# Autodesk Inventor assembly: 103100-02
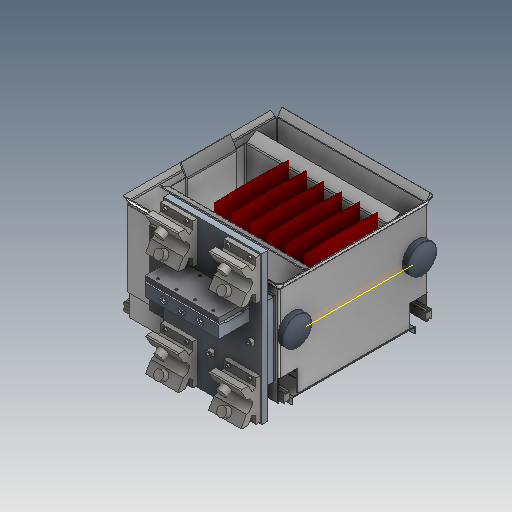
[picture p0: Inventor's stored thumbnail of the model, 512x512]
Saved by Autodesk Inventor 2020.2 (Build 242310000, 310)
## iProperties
Created: 2000-10
Part Number: 103100-02
Document SubType Name: Assembly
Designer: wymerj
Mass: 14269.6 g
Surface Area: 19861.8 cm^2
Volume: 4078.28 cm^3
Density: 3.49893 g/cm^3
Control State: 0
Master: False
Checked Out: False
Shininess: 0.0
Length Units: 11269
Angle Units: 11279
Time Units: 11290
Mass Units: 11283
Length Display Precision: 3
Angle Display Precision: 2
Compacted: True
Dimensions: 394,2x458,1x394,7 mm
Mass: 14,27 kg
DocNumber: ADSK-014244
Folder: 01 - Themengebiete\Simplification\01 - Packaging machine\
VDS_Category: 3D Komponenten
VDS_NumSchm: Autodesk
Density: 0.0
Volumn: 0.0
Area: 0.0
PropertySet Name: Model Information
Author: wymerj
Revision Number: -
Title: skid
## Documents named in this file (14)
- D:\07 - DEMODATEN\OTX 2019 - Dataset - UPDATE - Dez2019\Designs\07-Packing machine\103100-02.iam
- D:\07 - DEMODATEN\OTX 2019 - Dataset - UPDATE - Dez2019\Designs\07-Packing machine\500361.iam
- D:\07 - DEMODATEN\OTX 2019 - Dataset - UPDATE - Dez2019\Designs\07-Packing machine\500693.iam
- D:\07 - DEMODATEN\OTX 2019 - Dataset - UPDATE - Dez2019\Designs\07-Packing machine\Parts\ADSK-011742.ipt
- D:\07 - DEMODATEN\OTX 2019 - Dataset - UPDATE - Dez2019\Designs\07-Packing machine\Parts\ADSK-011668.ipt
- D:\07 - DEMODATEN\OTX 2019 - Dataset - UPDATE - Dez2019\Designs\07-Packing machine\Parts\ADSK-011673.ipt
- D:\07 - DEMODATEN\OTX 2019 - Dataset - UPDATE - Dez2019\Content Center Files\de-DE\DIN 125-1  B\DIN 125-1 - B 8,4.ipt
- D:\07 - DEMODATEN\OTX 2019 - Dataset - UPDATE - Dez2019\Content Center Files\de-DE\ISO 4762(2)\ISO 4762 - M8 x 25ISO.ipt
- D:\07 - DEMODATEN\OTX 2019 - Dataset - UPDATE - Dez2019\Content Center Files\de-DE\ISO 4762(2)\ISO 4762 - M8 x 80ISO.ipt
- D:\07 - DEMODATEN\OTX 2019 - Dataset - UPDATE - Dez2019\Content Center Files\de-DE\DIN 125-1  B\DIN 125-1 - B 4,3.ipt
- D:\07 - DEMODATEN\OTX 2019 - Dataset - UPDATE - Dez2019\Designs\07-Packing machine\Parts\ADSK-011759.ipt
- D:\07 - DEMODATEN\OTX 2019 - Dataset - UPDATE - Dez2019\Content Center Files\de-DE\ISO 4762(2)\ISO 4762 - M4 x 20ISO.ipt
- D:\07 - DEMODATEN\OTX 2019 - Dataset - UPDATE - Dez2019\Content Center Files\de-DE\ISO 4762(2)\ISO 4762 - M6 x 30ISO.ipt
- D:\07 - DEMODATEN\OTX 2019 - Dataset - UPDATE - Dez2019\Designs\07-Packing machine\ADSK-014245.iam
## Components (59 placed, 13 different names)
1. 500361:1 [sub-assembly] — Mate:1, Mate:2, Mate:3, Insert:1, Mate:4, Insert:2, Mate:5, Insert:3, Mate:6, Insert:4, Mate:7, Passend:12, Passend:13, Passend:14
2. 500693:1 [sub-assembly] — Mate:1, Mate:2, Mate:3, Passend:66, Passend:67, Passend:68
3. ADSK-011742:1 — Insert:3, Mate:6
4. ADSK-011742:2 — Insert:1, Mate:4
5. ADSK-011742:3 — Insert:2, Mate:5
6. ADSK-011742:4 — Insert:4, Mate:7
7. ADSK-011668:1 — Passend:9, Passend:10, Passend:11, Passend:12, Passend:13, Passend:14, Passend:16, Passend:18, Passend:20, Passend:22, Passend:24, Passend:26, Passend:28, Passend:30, Passend:31, Passend:33
8. ADSK-011673:1 — Passend:9, Passend:10, Passend:11, Passend:32
9. ADSK-014245:1 [sub-assembly] — Passend:66, Passend:67, Passend:68
10. ADSK-011759:1 — Passend:31, Passend:32, Passend:33
11. ISO 4762 M4 x 20:1 — Passend:35
12. ISO 4762 M4 x 20:2 — Passend:37
13. ISO 4762 M4 x 20:3 — Passend:39
14. ISO 4762 M4 x 20:4 — Passend:41
15. ISO 4762 M4 x 20:5 — Passend:43
16. ISO 4762 M4 x 20:6 — Passend:45
17. ISO 4762 M4 x 20:7 — Passend:47
18. ISO 4762 M4 x 20:8 — Passend:49
19. ISO 4762 M4 x 20:9 — Passend:51
20. ISO 4762 M4 x 20:10 — Passend:53
21. ISO 4762 M4 x 20:11 — Passend:55
22. ISO 4762 M4 x 20:12 — Passend:57
23. ISO 4762 M4 x 20:13 — Passend:59
24. ISO 4762 M4 x 20:14 — Passend:61
25. ISO 4762 M4 x 20:15 — Passend:63
26. ISO 4762 M4 x 20:16 — Passend:65
27. DIN 125-1 B B 8,4:1
28. DIN 125-1 B B 8,4:3
29. DIN 125-1 B B 8,4:4
30. ISO 4762 M8 x 25:1
31. ISO 4762 M8 x 25:2
32. ISO 4762 M8 x 25:3
33. ISO 4762 M8 x 80:1
34. ISO 4762 M8 x 80:2
35. ISO 4762 M8 x 80:3
36. DIN 125-1 B B 4,3:1
37. DIN 125-1 B B 4,3:2 — Passend:51, Passend:53, Passend:55, Passend:57
38. DIN 125-1 B B 4,3:3
39. DIN 125-1 B B 4,3:4
40. DIN 125-1 B B 4,3:5
41. DIN 125-1 B B 4,3:6 — Passend:59, Passend:61, Passend:63, Passend:65
42. DIN 125-1 B B 4,3:7
43. DIN 125-1 B B 4,3:8
44. DIN 125-1 B B 4,3:9
45. DIN 125-1 B B 4,3:10
46. DIN 125-1 B B 4,3:11
47. DIN 125-1 B B 4,3:12 — Passend:43, Passend:45, Passend:47, Passend:49
48. DIN 125-1 B B 4,3:13
49. DIN 125-1 B B 4,3:14 — Passend:35, Passend:37, Passend:39, Passend:41
50. DIN 125-1 B B 4,3:15
51. DIN 125-1 B B 4,3:16
52. ISO 4762 M6 x 30:1 — Passend:16
53. ISO 4762 M6 x 30:2 — Passend:18
54. ISO 4762 M6 x 30:3 — Passend:20
55. ISO 4762 M6 x 30:4 — Passend:22
56. ISO 4762 M6 x 30:5 — Passend:24
57. ISO 4762 M6 x 30:6 — Passend:26
58. ISO 4762 M6 x 30:7 — Passend:28
59. ISO 4762 M6 x 30:8 — Passend:30
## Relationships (47: Mate 43, Insert 4)
- Mate:1: 500361:1 ↔ 500693:1
- Mate:2: 500361:1 ↔ 500693:1
- Mate:3: 500361:1 ↔ 500693:1
- Insert:1: 500361:1 ↔ ADSK-011742:2
- Mate:4: 500361:1 ↔ ADSK-011742:2
- Insert:2: 500361:1 ↔ ADSK-011742:3
- Mate:5: 500361:1 ↔ ADSK-011742:3
- Insert:3: 500361:1 ↔ ADSK-011742:1
- Mate:6: 500361:1 ↔ ADSK-011742:1
- Insert:4: 500361:1 ↔ ADSK-011742:4
- Mate:7: 500361:1 ↔ ADSK-011742:4
- Passend:9 [Mate]: ADSK-011668:1 ↔ ADSK-011673:1
- Passend:10 [Mate]: ADSK-011668:1 ↔ ADSK-011673:1
- Passend:11 [Mate]: ADSK-011668:1 ↔ ADSK-011673:1
- Passend:12 [Mate]: 500361:1 ↔ ADSK-011668:1
- Passend:13 [Mate]: 500361:1 ↔ ADSK-011668:1
- Passend:14 [Mate]: 500361:1 ↔ ADSK-011668:1
- Passend:16 [Mate]: ADSK-011668:1 ↔ ISO 4762 M6 x 30:1
- Passend:18 [Mate]: ADSK-011668:1 ↔ ISO 4762 M6 x 30:2
- Passend:20 [Mate]: ADSK-011668:1 ↔ ISO 4762 M6 x 30:3
- Passend:22 [Mate]: ADSK-011668:1 ↔ ISO 4762 M6 x 30:4
- Passend:24 [Mate]: ADSK-011668:1 ↔ ISO 4762 M6 x 30:5
- Passend:26 [Mate]: ADSK-011668:1 ↔ ISO 4762 M6 x 30:6
- Passend:28 [Mate]: ADSK-011668:1 ↔ ISO 4762 M6 x 30:7
- Passend:30 [Mate]: ADSK-011668:1 ↔ ISO 4762 M6 x 30:8
- Passend:31 [Mate]: ADSK-011668:1 ↔ ADSK-011759:1
- Passend:32 [Mate]: ADSK-011673:1 ↔ ADSK-011759:1
- Passend:33 [Mate]: ADSK-011668:1 ↔ ADSK-011759:1
- Passend:35 [Mate]: ISO 4762 M4 x 20:1 ↔ DIN 125-1 B B 4,3:14
- Passend:37 [Mate]: ISO 4762 M4 x 20:2 ↔ DIN 125-1 B B 4,3:14
- Passend:39 [Mate]: ISO 4762 M4 x 20:3 ↔ DIN 125-1 B B 4,3:14
- Passend:41 [Mate]: ISO 4762 M4 x 20:4 ↔ DIN 125-1 B B 4,3:14
- Passend:43 [Mate]: ISO 4762 M4 x 20:5 ↔ DIN 125-1 B B 4,3:12
- Passend:45 [Mate]: ISO 4762 M4 x 20:6 ↔ DIN 125-1 B B 4,3:12
- Passend:47 [Mate]: ISO 4762 M4 x 20:7 ↔ DIN 125-1 B B 4,3:12
- Passend:49 [Mate]: ISO 4762 M4 x 20:8 ↔ DIN 125-1 B B 4,3:12
- Passend:51 [Mate]: ISO 4762 M4 x 20:9 ↔ DIN 125-1 B B 4,3:2
- Passend:53 [Mate]: ISO 4762 M4 x 20:10 ↔ DIN 125-1 B B 4,3:2
- Passend:55 [Mate]: ISO 4762 M4 x 20:11 ↔ DIN 125-1 B B 4,3:2
- Passend:57 [Mate]: ISO 4762 M4 x 20:12 ↔ DIN 125-1 B B 4,3:2
- Passend:59 [Mate]: ISO 4762 M4 x 20:13 ↔ DIN 125-1 B B 4,3:6
- Passend:61 [Mate]: ISO 4762 M4 x 20:14 ↔ DIN 125-1 B B 4,3:6
- Passend:63 [Mate]: ISO 4762 M4 x 20:15 ↔ DIN 125-1 B B 4,3:6
- Passend:65 [Mate]: ISO 4762 M4 x 20:16 ↔ DIN 125-1 B B 4,3:6
- Passend:66 [Mate]: 500693:1 ↔ ADSK-014245:1
- Passend:67 [Mate]: 500693:1 ↔ ADSK-014245:1
- Passend:68 [Mate]: 500693:1 ↔ ADSK-014245:1
